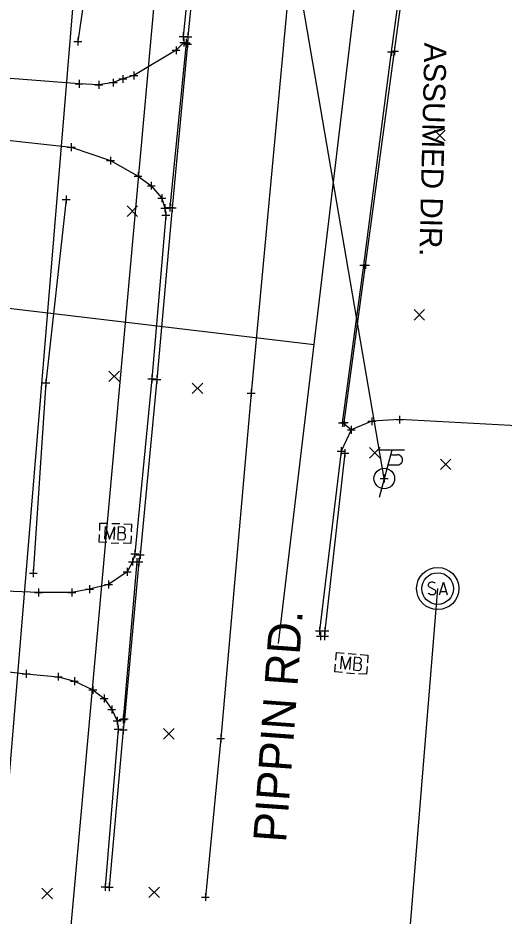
# Model space of a CAD drawing. Extents: x 1380440 to 1381945, y 468756 to 470369.
# Drawn here: x 1381494.5 to 1381555.9, y 468998.9 to 469112.5 of the extents above; entities that cross this region are included whole.
import ezdxf

# ---------------------------------------------------------------- set-up
doc = ezdxf.new("R2010")
doc.units = 0
for name, color, linetype in [('DR_X_Cells', 7, 'Continuous'), ('GE_P_Driveway_CL', 7, 'Continuous'), ('PM_X_CL_Double_Solid', 7, 'Continuous'), ('PV_P_Curb_Ramp', 7, 'Continuous'), ('PV_P_EOP', 7, 'Continuous'), ('PV_X_COP', 7, 'Continuous'), ('RD_P_Cells', 7, 'Continuous'), ('RW_P_Esmt_TMP', 7, 'Continuous'), ('RW_X_CL', 7, 'Continuous'), ('RW_X_Esmt_SH', 7, 'Continuous'), ('SC_Scratch2', 7, 'Continuous'), ('SC_Shading1', 7, 'Continuous'), ('SH_Named_Boundary', 7, 'Continuous'), ('UT_X_Gas', 7, 'Continuous'), ('UT_X_Overhead_Combined', 7, 'Continuous'), ('UT_X_Sanitary_Line', 7, 'Continuous'), ('UT_X_Water', 7, 'Continuous'), ('X-CL', 7, 'Continuous'), ('X-SUBDIVISION', 7, 'Continuous')]:
    doc.layers.add(name, color=color, linetype=linetype)

msp = doc.modelspace()

# ---------------------------------------------------------------- linework, layer by layer
at = {"layer": 'DR_X_Cells'}
for points in [[(1381518, 469135.71), (1381515.36, 469110.2), (1381515.44, 469109.41)], [(1381513.05, 469088.48), (1381513.17, 469087.56), (1381511.42, 469066.88), (1381509.25, 469044.75), (1381508.96, 469043.74)], [(1381535.81, 469057.46), (1381533.28, 469034.97), (1381533.26, 469034.32)], [(1381507.02, 469023.6), (1381507.17, 469022.55), (1381505.52, 469002.58)]]:
    msp.add_lwpolyline(points, dxfattribs=at)
at = {"layer": 'GE_P_Driveway_CL'}
for p, q in [((1381547.14, 469097), (1381548.48, 469098.34)), ((1381547.14, 469098.34), (1381548.48, 469097)), ((1381508.28, 469087.42), (1381509.61, 469088.75)), ((1381508.28, 469088.75), (1381509.61, 469087.42)), ((1381544.56, 469074.3), (1381545.89, 469075.63)), ((1381544.56, 469075.63), (1381545.89, 469074.3)), ((1381505.98, 469066.52), (1381507.32, 469067.85)), ((1381505.98, 469067.85), (1381507.32, 469066.52)), ((1381516.52, 469065.01), (1381517.86, 469066.34)), ((1381516.52, 469066.34), (1381517.86, 469065.01)), ((1381538.94, 469056.83), (1381540.28, 469058.17)), ((1381538.94, 469058.17), (1381540.28, 469056.83)), ((1381547.89, 469055.39), (1381549.22, 469056.72)), ((1381547.89, 469056.72), (1381549.22, 469055.39)), ((1381512.89, 469021.28), (1381514.22, 469022.62)), ((1381512.89, 469022.62), (1381514.22, 469021.28)), ((1381497.51, 469001.09), (1381498.84, 469002.42)), ((1381497.51, 469002.42), (1381498.84, 469001.09)), ((1381511.04, 469001.23), (1381512.38, 469002.56)), ((1381511.04, 469002.56), (1381512.38, 469001.23))]:
    msp.add_line(p, q, dxfattribs=at)
at = {"layer": 'PM_X_CL_Double_Solid'}
msp.add_lwpolyline([(1381555.39, 469442.03), (1381550.97, 469391.02), (1381547.28, 469345.9), (1381541.95, 469289.55), (1381537.19, 469231.27), (1381533.05, 469168.09), (1381530.32, 469133.74), (1381523.97, 469065.08), (1381520.12, 469021.37), (1381518.18, 469001.31)], dxfattribs=at)
at = {"layer": 'PV_P_Curb_Ramp'}
for p, q in [((1381547.56, 469042.34), (1381547.56, 469042.34)), ((1381547.56, 469040.34), (1381547.56, 469040.34)), ((1381547.56, 469040.34), (1381547.56, 469040.34)), ((1381547.56, 469040.34), (1381547.56, 469040.34)), ((1381547.56, 469038.34), (1381547.56, 469038.34))]:
    msp.add_line(p, q, dxfattribs=at)
msp.add_circle((1381547.56, 469040.34), 2, dxfattribs=at)
at = {"layer": 'PV_P_EOP'}
for points in [[(1381547.23, 469041.02), (1381547.21, 469041.05), (1381547.17, 469041.07), (1381547.06, 469041.11), (1381546.92, 469041.14), (1381546.82, 469041.14), (1381546.78, 469041.14), (1381546.61, 469041.1), (1381546.48, 469041.02), (1381546.39, 469040.92), (1381546.36, 469040.82), (1381546.36, 469040.74), (1381546.39, 469040.64), (1381546.49, 469040.56), (1381547.18, 469040.18), (1381547.24, 469040.13), (1381547.27, 469040.08), (1381547.29, 469040), (1381547.29, 469039.93), (1381547.28, 469039.85), (1381547.27, 469039.8), (1381547.24, 469039.74), (1381547.22, 469039.69), (1381547.19, 469039.65), (1381547.16, 469039.61), (1381547.12, 469039.59), (1381547.07, 469039.56), (1381547.03, 469039.55), (1381546.92, 469039.54), (1381546.74, 469039.54), (1381546.63, 469039.56), (1381546.46, 469039.65), (1381546.36, 469039.72)], [(1381547.77, 469039.54), (1381548.28, 469041.14), (1381548.77, 469039.54)], [(1381548.64, 469039.91), (1381547.9, 469039.91)]]:
    msp.add_lwpolyline(points, dxfattribs=at)
for radius in [2.67, 2]:
    msp.add_circle((1381547.56, 469040.34), radius, dxfattribs=at)
at = {"layer": 'PV_X_COP'}
for p, q in [((1381543.36, 469057.86), (1381540.16, 469057.86)), ((1381541.76, 469057.86), (1381540.16, 469051.86)), ((1381541.6, 469057.26), (1381542.45, 469057.26)), ((1381541.26, 469055.99), (1381542.45, 469055.99))]:
    msp.add_line(p, q, dxfattribs=at)
msp.add_circle((1381540.8, 469054.26), 1.3, dxfattribs=at)
msp.add_arc((1381542.47, 469056.63), 0.638, 268.8767, 91.1233, dxfattribs=at)
at = {"layer": 'RD_P_Cells'}
for p, q in [((1381506.35, 469048.58), (1381507.35, 469048.55)), ((1381506.81, 469047.34), (1381506.81, 469047.34)), ((1381506.26, 469046.14), (1381507.26, 469046.1)), ((1381536.24, 469032.12), (1381537.24, 469032.04)), ((1381536.65, 469030.87), (1381536.65, 469030.87)), ((1381536.04, 469029.69), (1381537.04, 469029.61))]:
    msp.add_line(p, q, dxfattribs=at)
for points in [[(1381504.82, 469047.67), (1381504.86, 469048.63), (1381505.83, 469048.6)], [(1381505.49, 469046.59), (1381505.55, 469048.19), (1381506.07, 469046.57), (1381506.68, 469048.15), (1381506.62, 469046.55)], [(1381507.84, 469047.38), (1381507.9, 469047.44), (1381507.94, 469047.47), (1381507.97, 469047.51), (1381507.98, 469047.53), (1381508.01, 469047.58), (1381508.02, 469047.62), (1381508.05, 469047.71), (1381508.05, 469047.75), (1381508.05, 469047.8), (1381508.04, 469047.87), (1381508.02, 469047.94), (1381507.98, 469047.99), (1381507.92, 469048.04), (1381507.87, 469048.07), (1381507.85, 469048.08), (1381507.79, 469048.11), (1381507.17, 469048.13), (1381507.11, 469046.53), (1381507.81, 469046.51), (1381507.9, 469046.55), (1381507.97, 469046.61), (1381508.04, 469046.71), (1381508.08, 469046.83), (1381508.1, 469046.94), (1381508.1, 469047.01), (1381508.08, 469047.09), (1381508.03, 469047.2), (1381507.97, 469047.28), (1381507.84, 469047.38), (1381507.14, 469047.4)], [(1381507.86, 469048.53), (1381508.86, 469048.49), (1381508.82, 469047.52)], [(1381505.74, 469046.16), (1381504.77, 469046.19), (1381504.81, 469047.16)], [(1381508.8, 469047.02), (1381508.77, 469046.05), (1381507.78, 469046.09)], [(1381534.68, 469031.28), (1381534.75, 469032.24), (1381535.72, 469032.17)], [(1381535.29, 469030.17), (1381535.42, 469031.77), (1381535.87, 469030.13), (1381536.55, 469031.68), (1381536.42, 469030.08)], [(1381537.67, 469030.85), (1381537.74, 469030.91), (1381537.78, 469030.95), (1381537.81, 469030.98), (1381537.82, 469031.01), (1381537.85, 469031.05), (1381537.87, 469031.09), (1381537.9, 469031.18), (1381537.9, 469031.21), (1381537.91, 469031.26), (1381537.9, 469031.34), (1381537.88, 469031.41), (1381537.85, 469031.46), (1381537.79, 469031.51), (1381537.74, 469031.54), (1381537.72, 469031.56), (1381537.66, 469031.59), (1381537.04, 469031.64), (1381536.91, 469030.04), (1381537.6, 469029.99), (1381537.7, 469030.03), (1381537.78, 469030.09), (1381537.85, 469030.18), (1381537.89, 469030.29), (1381537.91, 469030.4), (1381537.92, 469030.48), (1381537.9, 469030.56), (1381537.86, 469030.67), (1381537.8, 469030.75), (1381537.67, 469030.85), (1381536.98, 469030.91)], [(1381537.75, 469032), (1381538.74, 469031.92), (1381538.66, 469030.96)], [(1381535.52, 469029.73), (1381534.56, 469029.81), (1381534.64, 469030.78)], [(1381538.62, 469030.46), (1381538.54, 469029.49), (1381537.55, 469029.57)]]:
    msp.add_lwpolyline(points, dxfattribs=at)
at = {"layer": 'RW_P_Esmt_TMP'}
for points in [[(1381529.3, 469267.44), (1381526.47, 469232.31), (1381523.61, 469197.35), (1381523.61, 469196.13), (1381521.19, 469168.77), (1381520.16, 469156.66), (1381518.94, 469140.36), (1381518.51, 469135.77), (1381515.95, 469110.14), (1381515.91, 469109.22), (1381513.99, 469088.5), (1381512.04, 469066.8), (1381509.95, 469044.61), (1381509.76, 469043.72), (1381507.94, 469023.87), (1381507.81, 469022.45), (1381506.02, 469002.56)], [(1381558.32, 469060.89), (1381542.74, 469061.71), (1381539.22, 469061.5), (1381536.63, 469060.42), (1381535.51, 469061.29), (1381538.22, 469081.26), (1381541.7, 469108.24), (1381543.98, 469125.12), (1381545.06, 469127.61), (1381548.03, 469130), (1381551.28, 469131.88), (1381559.09, 469135.28)], [(1381535.75, 469061.36), (1381538.44, 469081.27), (1381542.11, 469108.32), (1381544.37, 469125.03), (1381545.21, 469127.46), (1381548.18, 469129.88), (1381551.46, 469131.85)], [(1381536.63, 469060.42), (1381535.33, 469057.72), (1381532.59, 469035), (1381532.73, 469034.31)]]:
    msp.add_lwpolyline(points, dxfattribs=at)
at = {"layer": 'RW_X_Esmt_SH'}
for points in [[(1381515.44, 469109.41), (1381514.47, 469108.44), (1381509.13, 469105.26), (1381507.75, 469104.81), (1381506.54, 469104.35), (1381504.72, 469104.06), (1381502.21, 469104.2), (1381488.02, 469105.3), (1381469.31, 469106.49)], [(1381515.44, 469109.41), (1381515.74, 469109.39), (1381513.68, 469088.55), (1381513.05, 469088.48)], [(1381465.96, 469099.1), (1381483.88, 469098.09), (1381501.2, 469096.18), (1381506.2, 469094.48), (1381509.67, 469092.51), (1381511.35, 469091.31), (1381512.69, 469089.74), (1381513.05, 469088.48)], [(1381508.96, 469043.74), (1381508.3, 469042.45), (1381505.95, 469040.85), (1381503.53, 469040.25), (1381501.31, 469039.83), (1381497.09, 469039.83), (1381476.12, 469040.68), (1381458.55, 469042.58)], [(1381508.96, 469043.74), (1381509.51, 469043.7), (1381507.77, 469023.76), (1381507.02, 469023.6)], [(1381457.62, 469033.36), (1381476.99, 469031.64), (1381495.52, 469029.54), (1381499.59, 469029.19), (1381501.62, 469028.61), (1381503.96, 469027.52), (1381505.39, 469026.42), (1381506.34, 469025.03), (1381507.02, 469023.6)]]:
    msp.add_lwpolyline(points, dxfattribs=at)
at = {"layer": 'SC_Scratch2'}
for points in [[(1381506.4, 469174), (1381505.9, 469138.98), (1381505.83, 469135.51), (1381502.06, 469109.54)], [(1381500.59, 469089.56), (1381498.03, 469066.37), (1381496.43, 469042.3)]]:
    msp.add_lwpolyline(points, dxfattribs=at)
at = {"layer": 'SC_Shading1'}
msp.add_lwpolyline([(1381555.39, 469442.03), (1381550.97, 469391.02), (1381547.28, 469345.9), (1381541.95, 469289.55), (1381537.19, 469231.27), (1381533.05, 469168.09), (1381530.32, 469133.74), (1381523.97, 469065.08), (1381520.12, 469021.37), (1381518.18, 469001.31)], dxfattribs=at)
at = {"layer": 'SH_Named_Boundary'}
for p, q in [((1381502.06, 469110.04), (1381502.06, 469109.04)), ((1381514.86, 469110.2), (1381515.86, 469110.2)), ((1381515.36, 469110.7), (1381515.36, 469109.7)), ((1381515.36, 469110.2), (1381515.36, 469110.2)), ((1381515.45, 469110.14), (1381516.45, 469110.14)), ((1381515.95, 469110.64), (1381515.95, 469109.64)), ((1381515.95, 469110.14), (1381515.95, 469110.14)), ((1381501.56, 469109.54), (1381502.56, 469109.54)), ((1381502.06, 469109.54), (1381502.06, 469109.54)), ((1381514.47, 469108.94), (1381514.47, 469107.94)), ((1381514.94, 469109.41), (1381515.94, 469109.41)), ((1381514.94, 469109.41), (1381515.94, 469109.41)), ((1381514.94, 469109.41), (1381515.94, 469109.41)), ((1381515.24, 469109.39), (1381516.24, 469109.39)), ((1381515.41, 469109.22), (1381516.41, 469109.22)), ((1381515.44, 469109.91), (1381515.44, 469108.91)), ((1381515.44, 469109.91), (1381515.44, 469108.91)), ((1381515.44, 469109.91), (1381515.44, 469108.91)), ((1381515.44, 469109.41), (1381515.44, 469109.41)), ((1381515.44, 469109.41), (1381515.44, 469109.41)), ((1381515.44, 469109.41), (1381515.44, 469109.41)), ((1381515.74, 469109.89), (1381515.74, 469108.89)), ((1381515.74, 469109.39), (1381515.74, 469109.39)), ((1381515.91, 469109.72), (1381515.91, 469108.72)), ((1381515.91, 469109.22), (1381515.91, 469109.22)), ((1381513.97, 469108.44), (1381514.97, 469108.44)), ((1381514.47, 469108.44), (1381514.47, 469108.44)), ((1381541.2, 469108.24), (1381542.2, 469108.24)), ((1381541.61, 469108.32), (1381542.61, 469108.32)), ((1381541.7, 469108.74), (1381541.7, 469107.74)), ((1381541.7, 469108.24), (1381541.7, 469108.24)), ((1381542.11, 469108.82), (1381542.11, 469107.82)), ((1381542.11, 469108.32), (1381542.11, 469108.32)), ((1381509.13, 469105.76), (1381509.13, 469104.76)), ((1381502.21, 469104.7), (1381502.21, 469103.7)), ((1381504.72, 469104.56), (1381504.72, 469103.56)), ((1381506.04, 469104.35), (1381507.04, 469104.35)), ((1381506.54, 469104.85), (1381506.54, 469103.85)), ((1381506.54, 469104.35), (1381506.54, 469104.35)), ((1381507.25, 469104.81), (1381508.25, 469104.81)), ((1381507.75, 469105.31), (1381507.75, 469104.31)), ((1381507.75, 469104.81), (1381507.75, 469104.81)), ((1381508.63, 469105.26), (1381509.63, 469105.26)), ((1381509.13, 469105.26), (1381509.13, 469105.26)), ((1381501.71, 469104.2), (1381502.71, 469104.2)), ((1381502.21, 469104.2), (1381502.21, 469104.2)), ((1381504.22, 469104.06), (1381505.22, 469104.06)), ((1381504.72, 469104.06), (1381504.72, 469104.06)), ((1381501.2, 469096.68), (1381501.2, 469095.68)), ((1381500.7, 469096.18), (1381501.7, 469096.18)), ((1381501.2, 469096.18), (1381501.2, 469096.18)), ((1381505.7, 469094.48), (1381506.7, 469094.48)), ((1381506.2, 469094.98), (1381506.2, 469093.98)), ((1381506.2, 469094.48), (1381506.2, 469094.48)), ((1381509.67, 469093.01), (1381509.67, 469092.01)), ((1381509.17, 469092.51), (1381510.17, 469092.51)), ((1381509.67, 469092.51), (1381509.67, 469092.51)), ((1381510.85, 469091.31), (1381511.85, 469091.31)), ((1381511.35, 469091.81), (1381511.35, 469090.81)), ((1381511.35, 469091.31), (1381511.35, 469091.31)), ((1381500.09, 469089.56), (1381501.09, 469089.56)), ((1381500.59, 469090.06), (1381500.59, 469089.06)), ((1381500.59, 469089.56), (1381500.59, 469089.56)), ((1381512.19, 469089.74), (1381513.19, 469089.74)), ((1381512.69, 469090.24), (1381512.69, 469089.24)), ((1381512.69, 469089.74), (1381512.69, 469089.74)), ((1381512.55, 469088.48), (1381513.55, 469088.48)), ((1381512.55, 469088.48), (1381513.55, 469088.48)), ((1381512.55, 469088.48), (1381513.55, 469088.48)), ((1381513.05, 469088.98), (1381513.05, 469087.98)), ((1381513.05, 469088.98), (1381513.05, 469087.98)), ((1381513.05, 469088.98), (1381513.05, 469087.98)), ((1381513.05, 469088.48), (1381513.05, 469088.48)), ((1381513.05, 469088.48), (1381513.05, 469088.48)), ((1381513.05, 469088.48), (1381513.05, 469088.48)), ((1381513.18, 469088.55), (1381514.18, 469088.55)), ((1381513.49, 469088.5), (1381514.49, 469088.5)), ((1381513.68, 469089.05), (1381513.68, 469088.05)), ((1381513.68, 469088.55), (1381513.68, 469088.55)), ((1381513.99, 469089), (1381513.99, 469088)), ((1381513.99, 469088.5), (1381513.99, 469088.5)), ((1381512.67, 469087.56), (1381513.67, 469087.56)), ((1381513.17, 469088.06), (1381513.17, 469087.06)), ((1381513.17, 469087.56), (1381513.17, 469087.56)), ((1381538.22, 469081.76), (1381538.22, 469080.76)), ((1381538.44, 469081.77), (1381538.44, 469080.77)), ((1381537.72, 469081.26), (1381538.72, 469081.26)), ((1381537.94, 469081.27), (1381538.94, 469081.27)), ((1381538.22, 469081.26), (1381538.22, 469081.26)), ((1381538.44, 469081.27), (1381538.44, 469081.27)), ((1381498.03, 469066.87), (1381498.03, 469065.87)), ((1381510.92, 469066.88), (1381511.92, 469066.88)), ((1381511.42, 469067.38), (1381511.42, 469066.38)), ((1381511.42, 469066.88), (1381511.42, 469066.88)), ((1381512.04, 469067.3), (1381512.04, 469066.3)), ((1381497.53, 469066.37), (1381498.53, 469066.37)), ((1381498.03, 469066.37), (1381498.03, 469066.37)), ((1381511.54, 469066.8), (1381512.54, 469066.8)), ((1381512.04, 469066.8), (1381512.04, 469066.8)), ((1381523.47, 469065.08), (1381524.47, 469065.08)), ((1381523.97, 469065.58), (1381523.97, 469064.58)), ((1381523.97, 469065.08), (1381523.97, 469065.08)), ((1381535.01, 469061.29), (1381536.01, 469061.29)), ((1381535.25, 469061.36), (1381536.25, 469061.36)), ((1381535.51, 469061.79), (1381535.51, 469060.79)), ((1381535.51, 469061.29), (1381535.51, 469061.29)), ((1381535.75, 469061.86), (1381535.75, 469060.86)), ((1381535.75, 469061.36), (1381535.75, 469061.36)), ((1381538.72, 469061.5), (1381539.72, 469061.5)), ((1381539.22, 469062), (1381539.22, 469061)), ((1381539.22, 469061.5), (1381539.22, 469061.5)), ((1381542.24, 469061.71), (1381543.24, 469061.71)), ((1381542.74, 469062.21), (1381542.74, 469061.21)), ((1381542.74, 469061.71), (1381542.74, 469061.71)), ((1381536.13, 469060.42), (1381537.13, 469060.42)), ((1381536.13, 469060.42), (1381537.13, 469060.42)), ((1381536.63, 469060.92), (1381536.63, 469059.92)), ((1381536.63, 469060.92), (1381536.63, 469059.92)), ((1381536.63, 469060.42), (1381536.63, 469060.42)), ((1381536.63, 469060.42), (1381536.63, 469060.42)), ((1381535.33, 469058.22), (1381535.33, 469057.22)), ((1381535.81, 469057.96), (1381535.81, 469056.96)), ((1381534.83, 469057.72), (1381535.83, 469057.72)), ((1381535.31, 469057.46), (1381536.31, 469057.46)), ((1381535.33, 469057.72), (1381535.33, 469057.72)), ((1381535.81, 469057.46), (1381535.81, 469057.46)), ((1381540.8, 469054.76), (1381540.8, 469053.76)), ((1381540.8, 469054.76), (1381540.8, 469053.76)), ((1381540.8, 469054.76), (1381540.8, 469053.76)), ((1381540.3, 469054.26), (1381541.3, 469054.26)), ((1381540.3, 469054.26), (1381541.3, 469054.26)), ((1381540.3, 469054.26), (1381541.3, 469054.26)), ((1381540.8, 469054.26), (1381540.8, 469054.26)), ((1381540.8, 469054.26), (1381540.8, 469054.26)), ((1381540.8, 469054.26), (1381540.8, 469054.26)), ((1381509.25, 469045.25), (1381509.25, 469044.25)), ((1381508.75, 469044.75), (1381509.75, 469044.75)), ((1381508.96, 469044.24), (1381508.96, 469043.24)), ((1381508.96, 469044.24), (1381508.96, 469043.24)), ((1381508.96, 469044.24), (1381508.96, 469043.24)), ((1381509.25, 469044.75), (1381509.25, 469044.75)), ((1381509.45, 469044.61), (1381510.45, 469044.61)), ((1381509.51, 469044.2), (1381509.51, 469043.2)), ((1381509.76, 469044.22), (1381509.76, 469043.22)), ((1381509.95, 469045.11), (1381509.95, 469044.11)), ((1381509.95, 469044.61), (1381509.95, 469044.61)), ((1381508.46, 469043.74), (1381509.46, 469043.74)), ((1381508.46, 469043.74), (1381509.46, 469043.74)), ((1381508.46, 469043.74), (1381509.46, 469043.74)), ((1381508.96, 469043.74), (1381508.96, 469043.74)), ((1381508.96, 469043.74), (1381508.96, 469043.74)), ((1381508.96, 469043.74), (1381508.96, 469043.74)), ((1381509.01, 469043.7), (1381510.01, 469043.7)), ((1381509.26, 469043.72), (1381510.26, 469043.72)), ((1381509.51, 469043.7), (1381509.51, 469043.7)), ((1381509.76, 469043.72), (1381509.76, 469043.72)), ((1381495.93, 469042.3), (1381496.93, 469042.3)), ((1381496.43, 469042.8), (1381496.43, 469041.8)), ((1381496.43, 469042.3), (1381496.43, 469042.3)), ((1381507.8, 469042.45), (1381508.8, 469042.45)), ((1381508.3, 469042.95), (1381508.3, 469041.95)), ((1381508.3, 469042.45), (1381508.3, 469042.45)), ((1381503.53, 469040.75), (1381503.53, 469039.75)), ((1381505.45, 469040.85), (1381506.45, 469040.85)), ((1381505.95, 469041.35), (1381505.95, 469040.35)), ((1381505.95, 469040.85), (1381505.95, 469040.85)), ((1381496.59, 469039.83), (1381497.59, 469039.83)), ((1381497.09, 469040.33), (1381497.09, 469039.33)), ((1381497.09, 469039.83), (1381497.09, 469039.83)), ((1381500.81, 469039.83), (1381501.81, 469039.83)), ((1381501.31, 469040.33), (1381501.31, 469039.33)), ((1381501.31, 469039.83), (1381501.31, 469039.83)), ((1381503.03, 469040.25), (1381504.03, 469040.25)), ((1381503.53, 469040.25), (1381503.53, 469040.25)), ((1381532.09, 469035), (1381533.09, 469035)), ((1381532.59, 469035.5), (1381532.59, 469034.5)), ((1381532.59, 469035), (1381532.59, 469035)), ((1381533.28, 469035.47), (1381533.28, 469034.47)), ((1381532.23, 469034.31), (1381533.23, 469034.31)), ((1381532.73, 469034.81), (1381532.73, 469033.81)), ((1381532.73, 469034.31), (1381532.73, 469034.31)), ((1381532.76, 469034.32), (1381533.76, 469034.32)), ((1381532.78, 469034.97), (1381533.78, 469034.97)), ((1381533.26, 469034.82), (1381533.26, 469033.82)), ((1381533.26, 469034.32), (1381533.26, 469034.32)), ((1381533.28, 469034.97), (1381533.28, 469034.97)), ((1381495.02, 469029.54), (1381496.02, 469029.54)), ((1381495.52, 469030.04), (1381495.52, 469029.04)), ((1381495.52, 469029.54), (1381495.52, 469029.54)), ((1381499.59, 469029.69), (1381499.59, 469028.69)), ((1381499.09, 469029.19), (1381500.09, 469029.19)), ((1381499.59, 469029.19), (1381499.59, 469029.19)), ((1381501.12, 469028.61), (1381502.12, 469028.61)), ((1381501.62, 469029.11), (1381501.62, 469028.11)), ((1381501.62, 469028.61), (1381501.62, 469028.61)), ((1381503.46, 469027.52), (1381504.46, 469027.52)), ((1381503.96, 469028.02), (1381503.96, 469027.02)), ((1381503.96, 469027.52), (1381503.96, 469027.52)), ((1381504.89, 469026.42), (1381505.89, 469026.42)), ((1381505.39, 469026.92), (1381505.39, 469025.92)), ((1381505.39, 469026.42), (1381505.39, 469026.42)), ((1381505.84, 469025.03), (1381506.84, 469025.03)), ((1381506.34, 469025.53), (1381506.34, 469024.53)), ((1381506.34, 469025.03), (1381506.34, 469025.03)), ((1381507.02, 469024.1), (1381507.02, 469023.1)), ((1381507.02, 469024.1), (1381507.02, 469023.1)), ((1381507.02, 469024.1), (1381507.02, 469023.1)), ((1381507.27, 469023.76), (1381508.27, 469023.76)), ((1381507.44, 469023.87), (1381508.44, 469023.87)), ((1381507.77, 469024.26), (1381507.77, 469023.26)), ((1381507.77, 469023.76), (1381507.77, 469023.76)), ((1381507.94, 469024.37), (1381507.94, 469023.37)), ((1381507.94, 469023.87), (1381507.94, 469023.87)), ((1381506.52, 469023.6), (1381507.52, 469023.6)), ((1381506.52, 469023.6), (1381507.52, 469023.6)), ((1381506.52, 469023.6), (1381507.52, 469023.6)), ((1381506.67, 469022.55), (1381507.67, 469022.55)), ((1381507.02, 469023.6), (1381507.02, 469023.6)), ((1381507.02, 469023.6), (1381507.02, 469023.6)), ((1381507.02, 469023.6), (1381507.02, 469023.6)), ((1381507.17, 469023.05), (1381507.17, 469022.05)), ((1381507.17, 469022.55), (1381507.17, 469022.55)), ((1381507.81, 469022.95), (1381507.81, 469021.95)), ((1381507.31, 469022.45), (1381508.31, 469022.45)), ((1381507.81, 469022.45), (1381507.81, 469022.45)), ((1381519.62, 469021.37), (1381520.62, 469021.37)), ((1381520.12, 469021.87), (1381520.12, 469020.87)), ((1381520.12, 469021.37), (1381520.12, 469021.37)), ((1381505.02, 469002.58), (1381506.02, 469002.58)), ((1381505.52, 469003.08), (1381505.52, 469002.08)), ((1381505.52, 469002.58), (1381505.52, 469002.58)), ((1381505.52, 469002.56), (1381506.52, 469002.56)), ((1381506.02, 469003.06), (1381506.02, 469002.06)), ((1381506.02, 469002.56), (1381506.02, 469002.56)), ((1381517.68, 469001.31), (1381518.68, 469001.31)), ((1381518.18, 469001.81), (1381518.18, 469000.81)), ((1381518.18, 469001.31), (1381518.18, 469001.31))]:
    msp.add_line(p, q, dxfattribs=at)
at = {"layer": 'UT_X_Gas'}
msp.add_lwpolyline([(1381485.9, 468926.41), (1381594.27, 470237.89), (1380558, 470279.29)], dxfattribs=at)
at = {"layer": 'UT_X_Overhead_Combined'}
msp.add_lwpolyline([(1381540.8, 469054.26), (1381515.28, 469203.1), (1381529.17, 469390.12), (1381543.86, 469565.78), (1381559.77, 469757.41), (1381571.97, 469887.64), (1381581.26, 470018.2), (1381595.79, 470220.83), (1381665.56, 470247.4)], dxfattribs=at)
at = {"layer": 'UT_X_Sanitary_Line'}
msp.add_line((1381524.42, 468755.72), (1381547.56, 469040.34), dxfattribs=at)
at = {"layer": 'UT_X_Water'}
for p, q in [((1381527.44, 469033.4), (1381542.5, 469159.93)), ((1381531.94, 469071.17), (1381484.29, 469076.84))]:
    msp.add_line(p, q, dxfattribs=at)
at = {"layer": 'X-CL'}
msp.add_line((1381528.04, 469296.45), (1381500.71, 468992.41), dxfattribs=at)

# ---------------------------------------------------------------- texts
at = {"layer": 'RW_X_CL'}
msp.add_text('ASSUMED DIR.', height=2.8, rotation=268.6571, dxfattribs=at).set_placement((1381545.88, 469109.42))
at = {"layer": 'X-SUBDIVISION'}
msp.add_text('PIPPIN RD.', height=4.167, rotation=85.8486, dxfattribs=at).set_placement((1381528.38, 469008.14))

doc.saveas('drawing.dxf')
